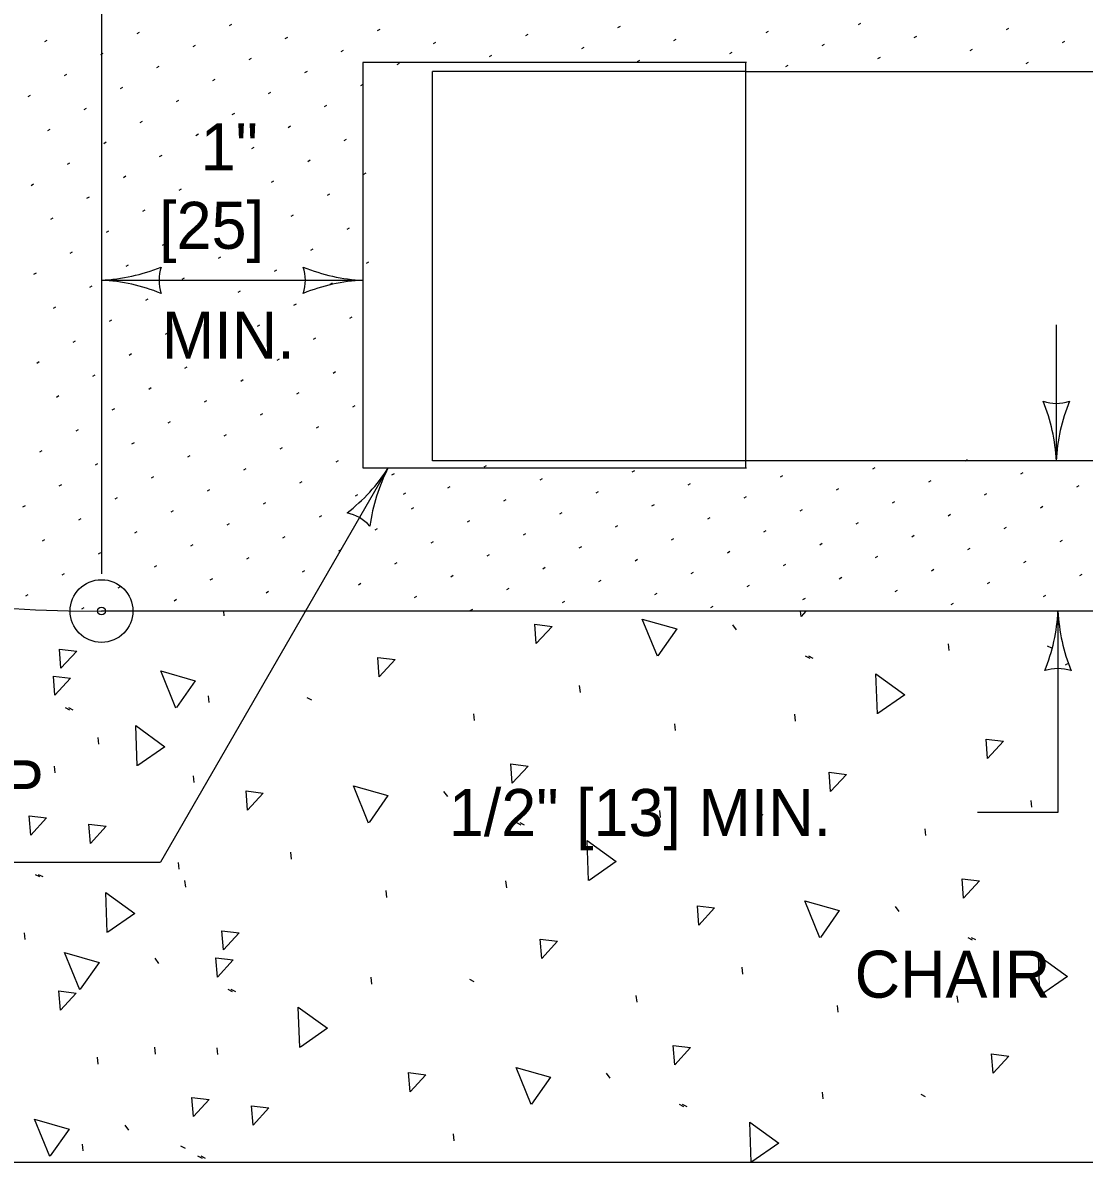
# Model space of a CAD drawing. Extents: x 49991.4 to 50021, y 49987.6 to 50011.4.
# Drawn here: x 50004.525 to 50005.88, y 49992.583 to 49994.036 of the extents above; entities that cross this region are included whole.
import ezdxf

# ---------------------------------------------------------------- set-up
doc = ezdxf.new("R2010")
doc.units = 0
for name, color, linetype in [('Level 1', 7, 'Continuous'), ('Level 2', 7, 'Continuous'), ('Level 20', 7, 'Continuous'), ('Level 3', 7, 'Continuous'), ('Level 4', 7, 'Continuous')]:
    doc.layers.add(name, color=color, linetype=linetype)

msp = doc.modelspace()

# ---------------------------------------------------------------- linework, layer by layer
at = {"layer": 'Level 1'}
for p, q in [((50005.4486, 49993.9852), (50004.9594, 49993.9852)), ((50004.9594, 49993.9852), (50004.9594, 49993.4684)), ((50005.4479, 49993.4684), (50005.4479, 49993.9852)), ((50005.4479, 49993.9739), (50008.0084, 49993.9739)), ((50006.0016, 49993.4772), (50005.4479, 49993.4772)), ((50004.9594, 49993.4684), (50005.4486, 49993.4684)), ((50011.4513, 49993.2857), (50004.6259, 49993.2857))]:
    msp.add_line(p, q, dxfattribs=at)
msp.add_lwpolyline([(50001.9803, 49992.5827), (50004.606, 49992.5827), (50014.3713, 49992.5827)], dxfattribs=at)
msp.add_ellipse((50004.6259, 49996.2377), major_axis=(0, -2.952), ratio=0.83118, start_param=5.208402, end_param=6.283185, dxfattribs=at)
at = {"layer": 'Level 20'}
msp.add_line((50004.9594, 49993.4784), (50004.9594, 49993.4784), dxfattribs=at)
at = {"layer": 'Level 3'}
for p, q in [((50004.6259, 49994.0829), (50004.6259, 49993.3332)), ((50004.6714, 49994.0223), (50004.6745, 49994.0241)), ((50004.7891, 49994.0325), (50004.7921, 49994.0343)), ((50004.9781, 49994.0262), (50004.9812, 49994.028)), ((50005.1671, 49994.0199), (50005.1702, 49994.0216)), ((50005.2848, 49994.0301), (50005.2878, 49994.0318)), ((50005.4738, 49994.0237), (50005.4769, 49994.0255)), ((50005.5915, 49994.0339), (50005.5945, 49994.0357)), ((50005.7805, 49994.0276), (50005.7836, 49994.0293)), ((50004.5538, 49994.0121), (50004.5568, 49994.0139)), ((50004.7428, 49994.0058), (50004.7458, 49994.0075)), ((50004.8604, 49994.016), (50004.8635, 49994.0177)), ((50005.0495, 49994.0097), (50005.0525, 49994.0114)), ((50005.3562, 49994.0135), (50005.3592, 49994.0153)), ((50005.5452, 49994.0072), (50005.5482, 49994.0089)), ((50005.6628, 49994.0174), (50005.6659, 49994.0191)), ((50005.8519, 49994.011), (50005.8549, 49994.0128)), ((50004.6251, 49993.9956), (50004.6281, 49993.9973)), ((50004.9318, 49993.9994), (50004.9348, 49994.0012)), ((50005.1208, 49993.9931), (50005.1238, 49993.9949)), ((50005.2385, 49994.0033), (50005.2415, 49994.0051)), ((50005.4275, 49993.997), (50005.4305, 49993.9987)), ((50005.6165, 49993.9906), (50005.6195, 49993.9924)), ((50005.7342, 49994.0008), (50005.7372, 49994.0026)), ((50004.6964, 49993.979), (50004.6995, 49993.9808)), ((50004.8141, 49993.9892), (50004.8171, 49993.991)), ((50005.0031, 49993.9829), (50005.0062, 49993.9847)), ((50005.3098, 49993.9868), (50005.3128, 49993.9885)), ((50005.4988, 49993.9804), (50005.5019, 49993.9822)), ((50005.8055, 49993.9843), (50005.8086, 49993.986)), ((50004.5788, 49993.9688), (50004.5818, 49993.9706)), ((50004.7678, 49993.9625), (50004.7708, 49993.9642)), ((50004.8854, 49993.9727), (50004.8885, 49993.9744)), ((50004.6501, 49993.9523), (50004.6531, 49993.954)), ((50004.9568, 49993.9561), (50004.9598, 49993.9579)), ((50004.5324, 49993.9421), (50004.5354, 49993.9438)), ((50004.7214, 49993.9357), (50004.7245, 49993.9375)), ((50004.8391, 49993.9459), (50004.8421, 49993.9477)), ((50004.6038, 49993.9255), (50004.6068, 49993.9273)), ((50004.7928, 49993.9192), (50004.7958, 49993.9209)), ((50004.9104, 49993.9294), (50004.9135, 49993.9311)), ((50004.6751, 49993.909), (50004.6781, 49993.9107)), ((50004.5574, 49993.8988), (50004.5604, 49993.9005)), ((50004.7464, 49993.8924), (50004.7495, 49993.8942)), ((50004.8641, 49993.9026), (50004.8671, 49993.9044)), ((50004.6288, 49993.8822), (50004.6318, 49993.884)), ((50004.8178, 49993.8759), (50004.8208, 49993.8776)), ((50004.9354, 49993.8861), (50004.9385, 49993.8878)), ((50004.7001, 49993.8657), (50004.7031, 49993.8674)), ((50004.5824, 49993.8555), (50004.5854, 49993.8572)), ((50004.7714, 49993.8491), (50004.7745, 49993.8509)), ((50004.8891, 49993.8593), (50004.8921, 49993.8611)), ((50004.6538, 49993.8389), (50004.6568, 49993.8407)), ((50004.8428, 49993.8326), (50004.8458, 49993.8343)), ((50004.9604, 49993.8428), (50004.9635, 49993.8445)), ((50004.5361, 49993.8287), (50004.5391, 49993.8305)), ((50004.7251, 49993.8224), (50004.7281, 49993.8241)), ((50004.9141, 49993.816), (50004.9171, 49993.8178)), ((50004.6074, 49993.8122), (50004.6104, 49993.8139)), ((50004.7964, 49993.8058), (50004.7995, 49993.8076)), ((50004.6788, 49993.7956), (50004.6818, 49993.7974)), ((50004.8678, 49993.7893), (50004.8708, 49993.791)), ((50004.5611, 49993.7854), (50004.5641, 49993.7872)), ((50004.7501, 49993.7791), (50004.7531, 49993.7808)), ((50004.9391, 49993.7727), (50004.9421, 49993.7745)), ((50004.6324, 49993.7689), (50004.6354, 49993.7706)), ((50004.8214, 49993.7625), (50004.8245, 49993.7643)), ((50004.7038, 49993.7523), (50004.7068, 49993.7541)), ((50004.8928, 49993.746), (50004.8958, 49993.7477)), ((50004.5861, 49993.7421), (50004.5891, 49993.7439)), ((50004.7751, 49993.7358), (50004.7781, 49993.7375)), ((50004.9641, 49993.7294), (50004.9671, 49993.7312)), ((50004.5397, 49993.7154), (50004.5428, 49993.7171)), ((50004.6574, 49993.7256), (50004.6604, 49993.7273)), ((50004.8464, 49993.7192), (50004.8495, 49993.721)), ((50004.7288, 49993.709), (50004.7318, 49993.7108)), ((50004.9178, 49993.7027), (50004.9208, 49993.7044)), ((50004.6111, 49993.6988), (50004.6141, 49993.7006)), ((50004.8001, 49993.6925), (50004.8031, 49993.6942)), ((50004.5647, 49993.6721), (50004.5678, 49993.6738)), ((50004.6824, 49993.6823), (50004.6854, 49993.684)), ((50004.8714, 49993.6759), (50004.8745, 49993.6777)), ((50004.7538, 49993.6657), (50004.7568, 49993.6675)), ((50004.9428, 49993.6594), (50004.9458, 49993.6611)), ((50004.6361, 49993.6555), (50004.6391, 49993.6573)), ((50004.8251, 49993.6492), (50004.8281, 49993.6509)), ((50005.844, 49993.6506), (50005.844, 49993.4772)), ((50004.5897, 49993.6288), (50004.5928, 49993.6305)), ((50004.7074, 49993.639), (50004.7104, 49993.6407)), ((50004.8964, 49993.6326), (50004.8995, 49993.6344)), ((50004.7788, 49993.6224), (50004.7818, 49993.6242)), ((50004.5434, 49993.602), (50004.5464, 49993.6038)), ((50004.6611, 49993.6122), (50004.6641, 49993.614)), ((50004.8501, 49993.6059), (50004.8531, 49993.6076)), ((50004.6147, 49993.5855), (50004.6178, 49993.5872)), ((50004.7324, 49993.5957), (50004.7354, 49993.5974)), ((50004.9214, 49993.5893), (50004.9245, 49993.5911)), ((50004.6861, 49993.5689), (50004.6891, 49993.5707)), ((50004.8038, 49993.5791), (50004.8068, 49993.5809)), ((50004.5684, 49993.5587), (50004.5714, 49993.5605)), ((50004.8751, 49993.5626), (50004.8781, 49993.5643)), ((50004.6397, 49993.5422), (50004.6428, 49993.5439)), ((50004.7574, 49993.5524), (50004.7604, 49993.5541)), ((50004.9464, 49993.546), (50004.9495, 49993.5478)), ((50004.7111, 49993.5256), (50004.7141, 49993.5274)), ((50004.8288, 49993.5358), (50004.8318, 49993.5376)), ((50004.5934, 49993.5154), (50004.5964, 49993.5172)), ((50004.9001, 49993.5193), (50004.9031, 49993.521)), ((50004.6647, 49993.4989), (50004.6678, 49993.5006)), ((50004.7824, 49993.5091), (50004.7854, 49993.5108)), ((50004.5471, 49993.4887), (50004.5501, 49993.4904)), ((50004.7361, 49993.4823), (50004.7391, 49993.4841)), ((50004.8538, 49993.4925), (50004.8568, 49993.4943)), ((50004.6184, 49993.4721), (50004.6214, 49993.4739)), ((50004.9251, 49993.476), (50004.9281, 49993.4777)), ((50005.1141, 49993.4696), (50005.1171, 49993.4714)), ((50005.7275, 49993.4774), (50005.7305, 49993.4791)), ((50004.6897, 49993.4556), (50004.6928, 49993.4573)), ((50004.9918, 49993.4684), (50004.7013, 49992.9653)), ((50004.8074, 49993.4658), (50004.8104, 49993.4675)), ((50004.9964, 49993.4594), (50004.9995, 49993.4612)), ((50005.1854, 49993.4531), (50005.1885, 49993.4548)), ((50005.3031, 49993.4633), (50005.3062, 49993.465)), ((50005.4921, 49993.4569), (50005.4952, 49993.4587)), ((50005.6098, 49993.4671), (50005.6128, 49993.4689)), ((50005.7988, 49993.4608), (50005.8019, 49993.4626)), ((50004.5721, 49993.4454), (50004.5751, 49993.4471)), ((50004.7611, 49993.439), (50004.7641, 49993.4408)), ((50004.8788, 49993.4492), (50004.8818, 49993.451)), ((50005.0678, 49993.4429), (50005.0708, 49993.4446)), ((50005.3745, 49993.4467), (50005.3775, 49993.4485)), ((50005.5635, 49993.4404), (50005.5665, 49993.4421)), ((50005.6812, 49993.4506), (50005.6842, 49993.4524)), ((50005.8702, 49993.4443), (50005.8732, 49993.446)), ((50004.6434, 49993.4288), (50004.6464, 49993.4306)), ((50004.9501, 49993.4327), (50004.9531, 49993.4344)), ((50005.0111, 49993.4348), (50005.0141, 49993.4366)), ((50005.1391, 49993.4263), (50005.1421, 49993.4281)), ((50005.2568, 49993.4365), (50005.2598, 49993.4383)), ((50005.4458, 49993.4302), (50005.4488, 49993.4319)), ((50005.6348, 49993.4238), (50005.6378, 49993.4256)), ((50005.7525, 49993.4341), (50005.7555, 49993.4358)), ((50004.5257, 49993.4186), (50004.5288, 49993.4203)), ((50004.7147, 49993.4123), (50004.7178, 49993.414)), ((50004.8324, 49993.4225), (50004.8354, 49993.4242)), ((50005.0214, 49993.4161), (50005.0245, 49993.4179)), ((50005.2104, 49993.4098), (50005.2135, 49993.4115)), ((50005.3281, 49993.42), (50005.3312, 49993.4217)), ((50005.5171, 49993.4136), (50005.5202, 49993.4154)), ((50005.8238, 49993.4175), (50005.8269, 49993.4193)), ((50004.5971, 49993.4021), (50004.6001, 49993.4038)), ((50004.7861, 49993.3957), (50004.7891, 49993.3975)), ((50004.9038, 49993.4059), (50004.9068, 49993.4077)), ((50005.0928, 49993.3996), (50005.0958, 49993.4013)), ((50005.3995, 49993.4034), (50005.4025, 49993.4052)), ((50005.5885, 49993.3971), (50005.5915, 49993.3988)), ((50005.7062, 49993.4073), (50005.7092, 49993.4091)), ((50004.6684, 49993.3855), (50004.6714, 49993.3873)), ((50004.9751, 49993.3894), (50004.9781, 49993.3911)), ((50005.1641, 49993.383), (50005.1671, 49993.3848)), ((50005.2818, 49993.3932), (50005.2848, 49993.395)), ((50005.4708, 49993.3869), (50005.4738, 49993.3886)), ((50005.6598, 49993.3805), (50005.6628, 49993.3823)), ((50005.7775, 49993.3908), (50005.7805, 49993.3925)), ((50004.5507, 49993.3753), (50004.5538, 49993.377)), ((50004.7397, 49993.369), (50004.7428, 49993.3707)), ((50004.8574, 49993.3792), (50004.8604, 49993.3809)), ((50005.0464, 49993.3728), (50005.0495, 49993.3746)), ((50005.2354, 49993.3665), (50005.2385, 49993.3682)), ((50005.3531, 49993.3767), (50005.3562, 49993.3784)), ((50005.5421, 49993.3703), (50005.5452, 49993.3721)), ((50005.8488, 49993.3742), (50005.8519, 49993.376)), ((50004.6221, 49993.3588), (50004.6251, 49993.3605)), ((50004.8111, 49993.3524), (50004.8141, 49993.3542)), ((50004.9288, 49993.3626), (50004.9318, 49993.3644)), ((50005.1178, 49993.3563), (50005.1208, 49993.358)), ((50005.4245, 49993.3601), (50005.4275, 49993.3619)), ((50005.6135, 49993.3538), (50005.6165, 49993.3555)), ((50005.7312, 49993.364), (50005.7342, 49993.3657)), ((50004.6934, 49993.3422), (50004.6964, 49993.344)), ((50005.0001, 49993.3461), (50005.0031, 49993.3478)), ((50005.1891, 49993.3397), (50005.1921, 49993.3415)), ((50005.3068, 49993.3499), (50005.3098, 49993.3517)), ((50005.4958, 49993.3436), (50005.4988, 49993.3453)), ((50005.6848, 49993.3372), (50005.6878, 49993.339)), ((50005.8025, 49993.3475), (50005.8055, 49993.3492)), ((50004.5757, 49993.332), (50004.5788, 49993.3337)), ((50004.7647, 49993.3257), (50004.7678, 49993.3274)), ((50004.8824, 49993.3359), (50004.8854, 49993.3376)), ((50005.0714, 49993.3295), (50005.0745, 49993.3313)), ((50005.2604, 49993.3232), (50005.2635, 49993.3249)), ((50005.3781, 49993.3334), (50005.3812, 49993.3351)), ((50005.5671, 49993.327), (50005.5702, 49993.3288)), ((50005.8738, 49993.3309), (50005.8769, 49993.3327)), ((50004.6471, 49993.3154), (50004.6501, 49993.3172)), ((50004.8361, 49993.3091), (50004.8391, 49993.3109)), ((50004.9538, 49993.3193), (50004.9568, 49993.3211)), ((50005.1428, 49993.313), (50005.1458, 49993.3147)), ((50005.4495, 49993.3168), (50005.4525, 49993.3186)), ((50005.6385, 49993.3105), (50005.6415, 49993.3122)), ((50005.7562, 49993.3207), (50005.7592, 49993.3224)), ((50004.5294, 49993.3052), (50004.5324, 49993.307)), ((50004.7184, 49993.2989), (50004.7214, 49993.3007)), ((50005.0251, 49993.3028), (50005.0281, 49993.3045)), ((50005.2141, 49993.2964), (50005.2171, 49993.2982)), ((50005.3318, 49993.3066), (50005.3348, 49993.3084)), ((50005.5208, 49993.3003), (50005.5238, 49993.302)), ((50005.7098, 49993.2939), (50005.7128, 49993.2957)), ((50005.8275, 49993.3042), (50005.8305, 49993.3059)), ((50004.6007, 49993.2887), (50004.6038, 49993.2904)), ((50005.0964, 49993.2862), (50005.0995, 49993.288)), ((50005.4031, 49993.2901), (50005.4062, 49993.2918)), ((50005.8461, 49993.2857), (50005.8461, 49993.0287)), ((50005.8555, 49993.2172), (50005.8586, 49993.219)), ((50005.8461, 49993.0287), (50005.7434, 49993.0287)), ((50003.6769, 49992.9653), (50004.7013, 49992.9653))]:
    msp.add_line(p, q, dxfattribs=at)
msp.add_lwpolyline([(50004.6259, 49993.7077), (50004.9594, 49993.7077)], dxfattribs=at)
for radius in [0.04, 0.005]:
    msp.add_circle((50004.6259, 49993.2857), radius, dxfattribs=at)
for centre, radius, start, end in [((50004.6144, 49993.9404), 0.233, 272.8273, 292.0772), ((50004.7541, 49993.7077), 0.0548, 162.1388, 197.8612), ((50004.9686, 49993.9298), 0.2223, 247.456, 267.6395), ((50004.8312, 49993.7077), 0.0548, 342.1388, 17.8612), ((50004.6167, 49993.4855), 0.2223, 67.456, 87.6395), ((50004.9709, 49993.475), 0.233, 92.8273, 112.0772), ((50005.844, 49993.6054), 0.0548, 252.1388, 287.8612), ((50005.6113, 49993.4657), 0.233, 2.8273, 22.0772), ((50006.0661, 49993.468), 0.2223, 157.456, 177.6395), ((50004.804, 49993.5874), 0.2223, 307.456, 327.6395), ((50005.199, 49993.362), 0.233, 152.8273, 172.0772), ((50004.9276, 49993.3574), 0.0548, 42.1388, 77.8612), ((50005.6239, 49993.2949), 0.2223, 337.456, 357.6395), ((50006.0788, 49993.2972), 0.233, 182.8273, 202.0772), ((50005.8461, 49993.1575), 0.0548, 72.1388, 107.8612)]:
    msp.add_arc(centre, radius, start, end, dxfattribs=at)
at = {"layer": 'Level 4'}
for p, q in [((50005.0481, 49993.4772), (50005.0481, 49993.9739)), ((50005.4473, 49993.9739), (50005.0481, 49993.9739)), ((50005.4479, 49993.4772), (50005.0481, 49993.4772)), ((50004.7825, 49993.2797), (50004.7819, 49993.2857)), ((50005.4308, 49993.2682), (50005.4356, 49993.2617)), ((50005.7075, 49993.2352), (50005.7066, 49993.2439)), ((50005.8321, 49993.2415), (50005.8378, 49993.2386)), ((50005.5237, 49993.2286), (50005.5294, 49993.2258)), ((50005.5278, 49993.2286), (50005.5335, 49993.2258)), ((50005.2368, 49993.182), (50005.2359, 49993.1907)), ((50004.7634, 49993.169), (50004.7624, 49993.1777)), ((50004.8879, 49993.1753), (50004.8936, 49993.1725)), ((50004.5795, 49993.1625), (50004.5852, 49993.1596)), ((50004.5836, 49993.1625), (50004.5893, 49993.1597)), ((50005.1017, 49993.146), (50005.1008, 49993.1547)), ((50005.5112, 49993.1454), (50005.5103, 49993.1541)), ((50005.3583, 49993.1332), (50005.3574, 49993.1418)), ((50004.6226, 49993.1158), (50004.6217, 49993.1245)), ((50004.567, 49993.0793), (50004.5661, 49993.088)), ((50004.7441, 49993.067), (50004.7432, 49993.0757)), ((50005.0624, 49993.0555), (50005.0672, 49993.049)), ((50005.8126, 49993.0354), (50005.8117, 49993.0441)), ((50005.3391, 49993.0225), (50005.3382, 49993.0312)), ((50005.4637, 49993.0288), (50005.4694, 49993.0259)), ((50005.1553, 49993.0159), (50005.161, 49993.0131)), ((50005.1594, 49993.016), (50005.1651, 49993.0131)), ((50005.6775, 49992.9994), (50005.6766, 49993.0081)), ((50004.8684, 49992.9693), (50004.8675, 49992.978)), ((50004.725, 49992.9564), (50004.724, 49992.9651)), ((50004.5411, 49992.9498), (50004.5468, 49992.947)), ((50004.5452, 49992.9498), (50004.5509, 49992.947)), ((50004.7333, 49992.9333), (50004.7324, 49992.942)), ((50005.1428, 49992.9327), (50005.1419, 49992.9414)), ((50004.9899, 49992.9205), (50004.989, 49992.9292)), ((50005.6382, 49992.909), (50005.643, 49992.9025)), ((50004.5286, 49992.8666), (50004.5277, 49992.8753)), ((50005.7311, 49992.8694), (50005.7368, 49992.8665)), ((50005.7352, 49992.8694), (50005.7409, 49992.8666)), ((50004.694, 49992.8428), (50004.6988, 49992.8363)), ((50005.4442, 49992.8227), (50005.4433, 49992.8314)), ((50004.9708, 49992.8098), (50004.9698, 49992.8185)), ((50005.0953, 49992.8161), (50005.101, 49992.8132)), ((50004.7869, 49992.8032), (50004.7926, 49992.8004)), ((50004.791, 49992.8033), (50004.7967, 49992.8004)), ((50005.3091, 49992.7868), (50005.3082, 49992.7955)), ((50005.7186, 49992.7862), (50005.7177, 49992.7949)), ((50005.5657, 49992.7739), (50005.5648, 49992.7826)), ((50004.695, 49992.7206), (50004.694, 49992.7293)), ((50004.7744, 49992.72), (50004.7735, 49992.7287)), ((50004.6215, 49992.7078), (50004.6206, 49992.7165)), ((50005.2698, 49992.6963), (50005.2746, 49992.6898)), ((50005.5466, 49992.6633), (50005.5456, 49992.6719)), ((50005.3627, 49992.6567), (50005.3684, 49992.6538)), ((50005.3668, 49992.6567), (50005.3725, 49992.6539)), ((50005.6711, 49992.6695), (50005.6768, 49992.6667)), ((50004.6557, 49992.6301), (50004.6604, 49992.6237)), ((50005.0758, 49992.61), (50005.0749, 49992.6187)), ((50004.6024, 49992.5971), (50004.6015, 49992.6058)), ((50004.7269, 49992.6034), (50004.7327, 49992.6006)), ((50004.7485, 49992.5906), (50004.7542, 49992.5877)), ((50004.7526, 49992.5906), (50004.7583, 49992.5877)), ((50004.9398, 49992.5827), (50004.9398, 49992.5828))]:
    msp.add_line(p, q, dxfattribs=at)
for points in [[(50005.5183, 49993.2788), (50005.5177, 49993.2857)], [(50005.5246, 49993.2857), (50005.5183, 49993.2788)], [(50005.1805, 49993.2443), (50005.1786, 49993.2689), (50005.2007, 49993.2662), (50005.1805, 49993.2443)], [(50005.335, 49993.228), (50005.3157, 49993.2755), (50005.3597, 49993.2629), (50005.3355, 49993.2287)], [(50004.5741, 49993.2127), (50004.5722, 49993.2372), (50004.5943, 49993.2346), (50004.5741, 49993.2127)], [(50004.9802, 49993.202), (50004.9783, 49993.2265), (50005.0004, 49993.2238), (50004.9802, 49993.202)], [(50004.7208, 49993.1619), (50004.7015, 49993.2094), (50004.7455, 49993.1968), (50004.7214, 49993.1626)], [(50004.5663, 49993.1782), (50004.5645, 49993.2027), (50004.5865, 49993.2001), (50004.5663, 49993.1782)], [(50005.6157, 49993.1545), (50005.6138, 49993.2057), (50005.6508, 49993.1789), (50005.6165, 49993.1549)], [(50004.6715, 49993.0883), (50004.6696, 49993.1395), (50004.7067, 49993.1127), (50004.6723, 49993.0888)], [(50005.7563, 49993.0978), (50005.7544, 49993.1223), (50005.7765, 49993.1197), (50005.7563, 49993.0978)], [(50005.1499, 49993.0661), (50005.148, 49993.0907), (50005.1701, 49993.088), (50005.1499, 49993.0661)], [(50005.556, 49993.0554), (50005.5541, 49993.08), (50005.5762, 49993.0773), (50005.556, 49993.0554)], [(50004.9666, 49993.0153), (50004.9473, 49993.0628), (50004.9913, 49993.0503), (50004.9672, 49993.016)], [(50004.8121, 49993.0316), (50004.8103, 49993.0562), (50004.8323, 49993.0535), (50004.8121, 49993.0316)], [(50004.5357, 49993), (50004.5338, 49993.0246), (50004.5559, 49993.0219), (50004.5357, 49993)], [(50004.6118, 49992.9893), (50004.6099, 49993.0138), (50004.632, 49993.0112), (50004.6118, 49992.9893)], [(50005.2473, 49992.9418), (50005.2454, 49992.993), (50005.2824, 49992.9662), (50005.2481, 49992.9422)], [(50005.7257, 49992.9196), (50005.7238, 49992.9441), (50005.7458, 49992.9415), (50005.7257, 49992.9196)], [(50004.6331, 49992.8757), (50004.6313, 49992.9269), (50004.6683, 49992.9), (50004.6339, 49992.8761)], [(50005.3879, 49992.8851), (50005.3861, 49992.9096), (50005.4081, 49992.907), (50005.3879, 49992.8851)], [(50005.5424, 49992.8688), (50005.5231, 49992.9162), (50005.5671, 49992.9037), (50005.543, 49992.8695)], [(50004.7815, 49992.8534), (50004.7796, 49992.878), (50004.8017, 49992.8753), (50004.7815, 49992.8534)], [(50005.1876, 49992.8427), (50005.1857, 49992.8673), (50005.2078, 49992.8646), (50005.1876, 49992.8427)], [(50004.5982, 49992.8026), (50004.5789, 49992.8501), (50004.6229, 49992.8376), (50004.5988, 49992.8033)], [(50005.8231, 49992.7952), (50005.8212, 49992.8464), (50005.8582, 49992.8196), (50005.8239, 49992.7957)], [(50004.7737, 49992.8189), (50004.7719, 49992.8435), (50004.7939, 49992.8408), (50004.7737, 49992.8189)], [(50004.5734, 49992.7766), (50004.5715, 49992.8011), (50004.5936, 49992.7985), (50004.5734, 49992.7766)], [(50004.8789, 49992.7291), (50004.877, 49992.7803), (50004.9141, 49992.7535), (50004.8797, 49992.7295)], [(50005.3573, 49992.7069), (50005.3554, 49992.7314), (50005.3775, 49992.7288), (50005.3573, 49992.7069)], [(50005.7634, 49992.6962), (50005.7615, 49992.7207), (50005.7836, 49992.7181), (50005.7634, 49992.6962)], [(50005.174, 49992.6561), (50005.1547, 49992.7036), (50005.1987, 49992.691), (50005.1746, 49992.6568)], [(50005.0195, 49992.6724), (50005.0177, 49992.6969), (50005.0397, 49992.6943), (50005.0195, 49992.6724)], [(50004.7431, 49992.6408), (50004.7412, 49992.6653), (50004.7633, 49992.6627), (50004.7431, 49992.6408)], [(50004.8192, 49992.63), (50004.8173, 49992.6546), (50004.8394, 49992.6519), (50004.8192, 49992.63)], [(50004.5598, 49992.59), (50004.5405, 49992.6374), (50004.5845, 49992.6249), (50004.5604, 49992.5906)], [(50005.4547, 49992.5827), (50005.4528, 49992.6338), (50005.4899, 49992.6069), (50005.4555, 49992.583)]]:
    msp.add_lwpolyline(points, dxfattribs=at)

# ---------------------------------------------------------------- texts
at = {"layer": 'Level 2'}
for s, p in [('1"', (50004.7524, 49993.8477)), ('[25]', (50004.6994, 49993.7477)), ('MIN.', (50004.7029, 49993.6077)), ('DOWEL BAR EXPANSION CAP', (50003.3932, 49993.0353)), ('1/2" [13] MIN.', (50005.069, 49992.9987)), ('CHAIR', (50005.5867, 49992.7925))]:
    msp.add_text(s, height=0.06, dxfattribs=at).set_placement(p)

doc.saveas('drawing.dxf')
